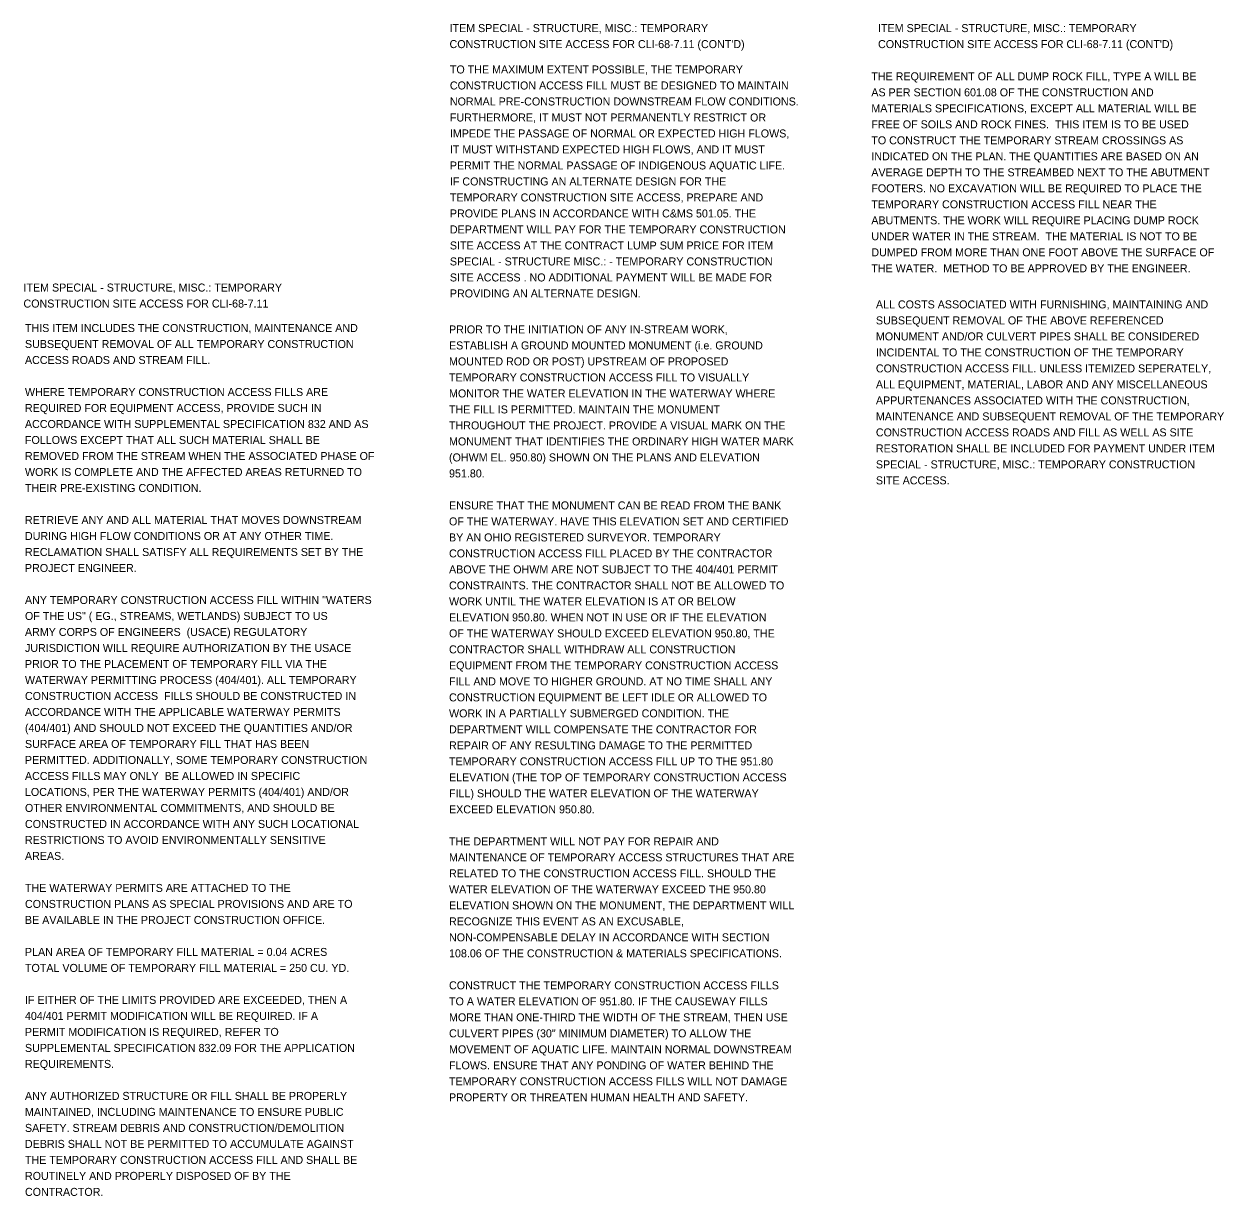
# Model space of a CAD drawing. Extents: x -15 to 144, y -80 to 40.
# Drawn here: x 123.08 to 144.08, y -80.42 to -59.91 of the extents above; entities that cross this region are included whole.
import ezdxf

# ---------------------------------------------------------------- set-up
doc = ezdxf.new("R2010")
doc.units = 0
doc.layers.add('BR_P_Gen_Text', color=7, linetype='Continuous')

msp = doc.modelspace()

# ---------------------------------------------------------------- texts
at = {"layer": 'BR_P_Gen_Text'}
for s, p in [('ITEM SPECIAL - STRUCTURE, MISC.: TEMPORARY ', (130.528, -60.05)), ('ITEM SPECIAL - STRUCTURE, MISC.: TEMPORARY ', (138.027, -60.05)), ("CONSTRUCTION SITE ACCESS FOR CLI-68-7.11 (CONT'D) ", (130.528, -60.33)), ("CONSTRUCTION SITE ACCESS FOR CLI-68-7.11 (CONT'D) ", (138.027, -60.33)), ('TO THE MAXIMUM EXTENT POSSIBLE, THE TEMPORARY ', (130.534, -60.774)), ('THE REQUIREMENT OF ALL DUMP ROCK FILL, TYPE A WILL BE ', (137.909, -60.894)), ('CONSTRUCTION ACCESS FILL MUST BE DESIGNED TO MAINTAIN ', (130.534, -61.054)), ('AS PER SECTION 601.08 OF THE CONSTRUCTION AND ', (137.909, -61.174)), ('NORMAL PRE-CONSTRUCTION DOWNSTREAM FLOW CONDITIONS. ', (130.534, -61.334)), ('MATERIALS SPECIFICATIONS, EXCEPT ALL MATERIAL WILL BE ', (137.909, -61.454)), ('FURTHERMORE, IT MUST NOT PERMANENTLY RESTRICT OR ', (130.534, -61.614)), ('FREE OF SOILS AND ROCK FINES.  THIS ITEM IS TO BE USED ', (137.909, -61.734)), ('IMPEDE THE PASSAGE OF NORMAL OR EXPECTED HIGH FLOWS, ', (130.534, -61.894)), ('TO CONSTRUCT THE TEMPORARY STREAM CROSSINGS AS ', (137.909, -62.014)), ('IT MUST WITHSTAND EXPECTED HIGH FLOWS, AND IT MUST ', (130.534, -62.174)), ('INDICATED ON THE PLAN. THE QUANTITIES ARE BASED ON AN ', (137.909, -62.294)), ('PERMIT THE NORMAL PASSAGE OF INDIGENOUS AQUATIC LIFE. ', (130.534, -62.454)), ('AVERAGE DEPTH TO THE STREAMBED NEXT TO THE ABUTMENT ', (137.909, -62.574)), ('IF CONSTRUCTING AN ALTERNATE DESIGN FOR THE ', (130.534, -62.734)), ('FOOTERS. NO EXCAVATION WILL BE REQUIRED TO PLACE THE ', (137.909, -62.854)), ('TEMPORARY CONSTRUCTION SITE ACCESS, PREPARE AND ', (130.534, -63.014)), ('TEMPORARY CONSTRUCTION ACCESS FILL NEAR THE ', (137.909, -63.134)), ('PROVIDE PLANS IN ACCORDANCE WITH C&MS 501.05. THE ', (130.534, -63.294)), ('ABUTMENTS. THE WORK WILL REQUIRE PLACING DUMP ROCK ', (137.909, -63.414)), ('DEPARTMENT WILL PAY FOR THE TEMPORARY CONSTRUCTION ', (130.534, -63.574)), ('UNDER WATER IN THE STREAM.  THE MATERIAL IS NOT TO BE ', (137.909, -63.694)), ('SITE ACCESS AT THE CONTRACT LUMP SUM PRICE FOR ITEM ', (130.534, -63.854)), ('DUMPED FROM MORE THAN ONE FOOT ABOVE THE SURFACE OF ', (137.909, -63.974)), ('SPECIAL - STRUCTURE MISC.: - TEMPORARY CONSTRUCTION ', (130.534, -64.134)), ('THE WATER.  METHOD TO BE APPROVED BY THE ENGINEER.', (137.909, -64.254)), ('ITEM SPECIAL - STRUCTURE, MISC.: TEMPORARY ', (123.072, -64.591)), ('SITE ACCESS . NO ADDITIONAL PAYMENT WILL BE MADE FOR ', (130.534, -64.414)), ('PROVIDING AN ALTERNATE DESIGN. ', (130.534, -64.694)), ('CONSTRUCTION SITE ACCESS FOR CLI-68-7.11 ', (123.072, -64.871)), ('ALL COSTS ASSOCIATED WITH FURNISHING, MAINTAINING AND ', (137.989, -64.886)), ('SUBSEQUENT REMOVAL OF THE ABOVE REFERENCED ', (137.989, -65.166)), ('THIS ITEM INCLUDES THE CONSTRUCTION, MAINTENANCE AND ', (123.098, -65.299)), ('PRIOR TO THE INITIATION OF ANY IN-STREAM WORK, ', (130.519, -65.324)), ('MONUMENT AND/OR CULVERT PIPES SHALL BE CONSIDERED ', (137.989, -65.446)), ('SUBSEQUENT REMOVAL OF ALL TEMPORARY CONSTRUCTION ', (123.098, -65.579)), ('ESTABLISH A GROUND MOUNTED MONUMENT (i.e. GROUND ', (130.519, -65.604)), ('ACCESS ROADS AND STREAM FILL. ', (123.098, -65.859)), ('INCIDENTAL TO THE CONSTRUCTION OF THE TEMPORARY ', (137.989, -65.726)), ('MOUNTED ROD OR POST) UPSTREAM OF PROPOSED ', (130.519, -65.884)), ('CONSTRUCTION ACCESS FILL. UNLESS ITEMIZED SEPERATELY, ', (137.989, -66.006)), ('TEMPORARY CONSTRUCTION ACCESS FILL TO VISUALLY ', (130.519, -66.164)), ('ALL EQUIPMENT, MATERIAL, LABOR AND ANY MISCELLANEOUS ', (137.989, -66.286)), ('WHERE TEMPORARY CONSTRUCTION ACCESS FILLS ARE ', (123.098, -66.419)), ('MONITOR THE WATER ELEVATION IN THE WATERWAY WHERE ', (130.519, -66.444)), ('REQUIRED FOR EQUIPMENT ACCESS, PROVIDE SUCH IN ', (123.098, -66.699)), ('APPURTENANCES ASSOCIATED WITH THE CONSTRUCTION, ', (137.989, -66.566)), ('THE FILL IS PERMITTED. MAINTAIN THE MONUMENT ', (130.519, -66.724)), ('MAINTENANCE AND SUBSEQUENT REMOVAL OF THE TEMPORARY ', (137.989, -66.846)), ('ACCORDANCE WITH SUPPLEMENTAL SPECIFICATION 832 AND AS ', (123.098, -66.979)), ('THROUGHOUT THE PROJECT. PROVIDE A VISUAL MARK ON THE ', (130.519, -67.004)), ('CONSTRUCTION ACCESS ROADS AND FILL AS WELL AS SITE ', (137.989, -67.126)), ('FOLLOWS EXCEPT THAT ALL SUCH MATERIAL SHALL BE ', (123.098, -67.259)), ('MONUMENT THAT IDENTIFIES THE ORDINARY HIGH WATER MARK ', (130.519, -67.284)), ('REMOVED FROM THE STREAM WHEN THE ASSOCIATED PHASE OF ', (123.098, -67.539)), ('RESTORATION SHALL BE INCLUDED FOR PAYMENT UNDER ITEM ', (137.989, -67.406)), ('(OHWM EL. 950.80) SHOWN ON THE PLANS AND ELEVATION', (130.519, -67.564)), ('SPECIAL - STRUCTURE, MISC.: TEMPORARY CONSTRUCTION ', (137.989, -67.686)), ('WORK IS COMPLETE AND THE AFFECTED AREAS RETURNED TO ', (123.098, -67.819)), ('951.80. ', (130.519, -67.844)), ('SITE ACCESS.', (137.989, -67.966)), ('THEIR PRE-EXISTING CONDITION.', (123.098, -68.099)), ('ENSURE THAT THE MONUMENT CAN BE READ FROM THE BANK ', (130.519, -68.404)), ('RETRIEVE ANY AND ALL MATERIAL THAT MOVES DOWNSTREAM ', (123.098, -68.659)), ('OF THE WATERWAY. HAVE THIS ELEVATION SET AND CERTIFIED ', (130.519, -68.684)), ('DURING HIGH FLOW CONDITIONS OR AT ANY OTHER TIME. ', (123.098, -68.939)), ('BY AN OHIO REGISTERED SURVEYOR. TEMPORARY ', (130.519, -68.964)), ('RECLAMATION SHALL SATISFY ALL REQUIREMENTS SET BY THE ', (123.098, -69.219)), ('CONSTRUCTION ACCESS FILL PLACED BY THE CONTRACTOR ', (130.519, -69.244)), ('PROJECT ENGINEER.', (123.098, -69.499)), ('ABOVE THE OHWM ARE NOT SUBJECT TO THE 404/401 PERMIT ', (130.519, -69.524)), ('CONSTRAINTS. THE CONTRACTOR SHALL NOT BE ALLOWED TO ', (130.519, -69.804)), ('ANY TEMPORARY CONSTRUCTION ACCESS FILL WITHIN "WATERS ', (123.098, -70.059)), ('WORK UNTIL THE WATER ELEVATION IS AT OR BELOW ', (130.519, -70.084)), ('OF THE US" ( EG., STREAMS, WETLANDS) SUBJECT TO US ', (123.098, -70.339)), ('ELEVATION 950.80. WHEN NOT IN USE OR IF THE ELEVATION ', (130.519, -70.364)), ('ARMY CORPS OF ENGINEERS  (USACE) REGULATORY ', (123.098, -70.619)), ('OF THE WATERWAY SHOULD EXCEED ELEVATION 950.80, THE ', (130.519, -70.644)), ('JURISDICTION WILL REQUIRE AUTHORIZATION BY THE USACE ', (123.098, -70.899)), ('CONTRACTOR SHALL WITHDRAW ALL CONSTRUCTION ', (130.519, -70.924)), ('PRIOR TO THE PLACEMENT OF TEMPORARY FILL VIA THE ', (123.098, -71.179)), ('EQUIPMENT FROM THE TEMPORARY CONSTRUCTION ACCESS ', (130.519, -71.204)), ('WATERWAY PERMITTING PROCESS (404/401). ALL TEMPORARY ', (123.098, -71.459)), ('FILL AND MOVE TO HIGHER GROUND. AT NO TIME SHALL ANY ', (130.519, -71.484)), ('CONSTRUCTION ACCESS  FILLS SHOULD BE CONSTRUCTED IN ', (123.098, -71.739)), ('CONSTRUCTION EQUIPMENT BE LEFT IDLE OR ALLOWED TO ', (130.519, -71.764)), ('ACCORDANCE WITH THE APPLICABLE WATERWAY PERMITS ', (123.098, -72.019)), ('WORK IN A PARTIALLY SUBMERGED CONDITION. THE ', (130.519, -72.044)), ('(404/401) AND SHOULD NOT EXCEED THE QUANTITIES AND/OR ', (123.098, -72.299)), ('DEPARTMENT WILL COMPENSATE THE CONTRACTOR FOR ', (130.519, -72.324)), ('SURFACE AREA OF TEMPORARY FILL THAT HAS BEEN ', (123.098, -72.579)), ('REPAIR OF ANY RESULTING DAMAGE TO THE PERMITTED ', (130.519, -72.604)), ('PERMITTED. ADDITIONALLY, SOME TEMPORARY CONSTRUCTION ', (123.098, -72.859)), ('TEMPORARY CONSTRUCTION ACCESS FILL UP TO THE 951.80 ', (130.519, -72.884)), ('ACCESS FILLS MAY ONLY  BE ALLOWED IN SPECIFIC ', (123.098, -73.139)), ('ELEVATION (THE TOP OF TEMPORARY CONSTRUCTION ACCESS ', (130.519, -73.164)), ('LOCATIONS, PER THE WATERWAY PERMITS (404/401) AND/OR ', (123.098, -73.419)), ('FILL) SHOULD THE WATER ELEVATION OF THE WATERWAY ', (130.519, -73.444)), ('OTHER ENVIRONMENTAL COMMITMENTS, AND SHOULD BE ', (123.098, -73.699)), ('EXCEED ELEVATION 950.80.', (130.519, -73.724)), ('CONSTRUCTED IN ACCORDANCE WITH ANY SUCH LOCATIONAL ', (123.098, -73.979)), ('RESTRICTIONS TO AVOID ENVIRONMENTALLY SENSITIVE ', (123.098, -74.259)), ('THE DEPARTMENT WILL NOT PAY FOR REPAIR AND ', (130.519, -74.284)), ('AREAS. ', (123.098, -74.539)), ('MAINTENANCE OF TEMPORARY ACCESS STRUCTURES THAT ARE ', (130.519, -74.564)), ('RELATED TO THE CONSTRUCTION ACCESS FILL. SHOULD THE ', (130.519, -74.844)), ('THE WATERWAY PERMITS ARE ATTACHED TO THE ', (123.098, -75.099)), ('WATER ELEVATION OF THE WATERWAY EXCEED THE 950.80 ', (130.519, -75.124)), ('CONSTRUCTION PLANS AS SPECIAL PROVISIONS AND ARE TO ', (123.098, -75.379)), ('ELEVATION SHOWN ON THE MONUMENT, THE DEPARTMENT WILL ', (130.519, -75.404)), ('BE AVAILABLE IN THE PROJECT CONSTRUCTION OFFICE. ', (123.098, -75.659)), ('RECOGNIZE THIS EVENT AS AN EXCUSABLE, ', (130.519, -75.684)), ('NON-COMPENSABLE DELAY IN ACCORDANCE WITH SECTION ', (130.519, -75.964)), ('PLAN AREA OF TEMPORARY FILL MATERIAL = 0.04 ACRES ', (123.098, -76.219)), ('108.06 OF THE CONSTRUCTION & MATERIALS SPECIFICATIONS.', (130.519, -76.244)), ('TOTAL VOLUME OF TEMPORARY FILL MATERIAL = 250 CU. YD. ', (123.098, -76.499)), ('CONSTRUCT THE TEMPORARY CONSTRUCTION ACCESS FILLS ', (130.519, -76.804)), ('IF EITHER OF THE LIMITS PROVIDED ARE EXCEEDED, THEN A ', (123.098, -77.059)), ('TO A WATER ELEVATION OF 951.80. IF THE CAUSEWAY FILLS ', (130.519, -77.084)), ('404/401 PERMIT MODIFICATION WILL BE REQUIRED. IF A ', (123.098, -77.339)), ('MORE THAN ONE-THIRD THE WIDTH OF THE STREAM, THEN USE ', (130.519, -77.364)), ('PERMIT MODIFICATION IS REQUIRED, REFER TO ', (123.098, -77.619)), ('CULVERT PIPES (30" MINIMUM DIAMETER) TO ALLOW THE ', (130.519, -77.644)), ('SUPPLEMENTAL SPECIFICATION 832.09 FOR THE APPLICATION ', (123.098, -77.899)), ('MOVEMENT OF AQUATIC LIFE. MAINTAIN NORMAL DOWNSTREAM ', (130.519, -77.924)), ('REQUIREMENTS.', (123.098, -78.179)), ('FLOWS. ENSURE THAT ANY PONDING OF WATER BEHIND THE ', (130.519, -78.204)), ('TEMPORARY CONSTRUCTION ACCESS FILLS WILL NOT DAMAGE ', (130.519, -78.484)), ('ANY AUTHORIZED STRUCTURE OR FILL SHALL BE PROPERLY ', (123.098, -78.739)), ('PROPERTY OR THREATEN HUMAN HEALTH AND SAFETY.', (130.519, -78.764)), ('MAINTAINED, INCLUDING MAINTENANCE TO ENSURE PUBLIC ', (123.098, -79.019)), ('SAFETY. STREAM DEBRIS AND CONSTRUCTION/DEMOLITION ', (123.098, -79.299)), ('DEBRIS SHALL NOT BE PERMITTED TO ACCUMULATE AGAINST ', (123.098, -79.579)), ('THE TEMPORARY CONSTRUCTION ACCESS FILL AND SHALL BE ', (123.098, -79.859)), ('ROUTINELY AND PROPERLY DISPOSED OF BY THE ', (123.098, -80.139)), ('CONTRACTOR.', (123.098, -80.419))]:
    msp.add_text(s, height=0.14, dxfattribs=at).set_placement(p)

doc.saveas('drawing.dxf')
